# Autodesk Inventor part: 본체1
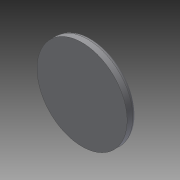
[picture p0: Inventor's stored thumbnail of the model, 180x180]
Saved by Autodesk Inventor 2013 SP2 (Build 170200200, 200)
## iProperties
Created: 2024-08
Part Number: 본체1
Material: Generic
Document SubType Name: Modeling
Designer: a
Density: 1 g/cm^3
Author: a
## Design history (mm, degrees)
sketch "스케치1"
  geometry: C1 r 71 at (0, 0); 1 further point
  constraints: 1 centre point, 1 coincident
  dimensions: "d0" = 142 diameter of C1
extrude "돌출1" new body sketch "스케치1" distance "d2" = 15; taper "d3" = 0 deg
fillet "모깎기2" dims "d5" = 6
sketch "스케치2"
  geometry: L1 (-20, 40.5)-(20, 40.5); L2 (20, 40.5)-(20, -40.5); L3 (20, -40.5)-(-20, -40.5); L4 (-20, -40.5)-(-20, 40.5); L5 (-20, 40.5)-(20, -40.5); L6 (20, 40.5)-(-20, -40.5); C1 r 65 at (0, 0) reference
  constraints: 12 end point, 2 midpoint, 2 parallel, 1 horizontal, 1 perpendicular
  dimensions: "d6" = 40 distance of L1.start L1.end; "d8" = 81 distance of L1.end L2.end
extrude "돌출2" join sketch "스케치2" distance "d9" = 10; taper "d10" = 0 deg
node "솔리드1"
